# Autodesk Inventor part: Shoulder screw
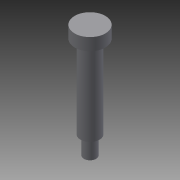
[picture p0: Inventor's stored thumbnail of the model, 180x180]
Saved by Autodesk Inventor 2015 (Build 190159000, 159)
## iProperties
Created: 2013-01
Part Number: Shoulder screw
Material: Iron, Cast
Document SubType Name: Modeling
Designer: CADCIM
Density: 7.25 g/cm^3
Appearance: Iron - Cast
Mass: 8.82983 g
Surface Area: 8.88285 cm^2
Volume: 1.21791 cm^3
Author: CADCIM
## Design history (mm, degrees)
sketch "Sketch1"
  geometry: L1 (0, 0)-(5, 0); L2 (5, 0)-(5, -4); L3 (3.125, -4)-(3.125, -31); L4 (5, -4)-(3.125, -4); L5 (3.125, -31)-(2, -31); L6 (2, -31)-(2, -37); L7 (2, -37)-(0, -37); L8 (0, -37)-(0, 0)
  constraints: 16 end point, 5 perpendicular, 1 horizontal, 1 parallel
  dimensions: "d0" = 5 distance of L1.start L1.end; "d4" = 3.125 horizontal distance of L1.start L3.start; "d5" = 4 distance of L1.end L2.end; "d6" = 27 vertical distance of L3.end L2.end; "d9" = 2 distance of L7.end L6.end; "d10" = 6 distance of L5.end L6.end
revolve "Revolution1" sketch "Sketch1" stored, may be unused: angle "d11" = 90 deg
body "Solid1"
